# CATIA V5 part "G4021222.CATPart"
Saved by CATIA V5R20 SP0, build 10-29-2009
Part number: G4021222
Revision: 7
Definition: design
Nomenclature: G4021222
Source: made
Description: NOT SPECIFIED
Bounding box of the stored display mesh (mm): x -9 to 22, y -10.833 to 10.833, z -11 to 11
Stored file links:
  C:\Users\Raffaele\Desktop\3D X SITO CF\BOLEX\26-BUSH REF 402\G4021222.CATPart
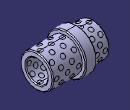
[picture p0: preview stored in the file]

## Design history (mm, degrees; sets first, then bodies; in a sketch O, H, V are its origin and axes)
Body1 "MANIFOLD_SOLID_BREP #8473" (main body)
  Solid1: solid without history
Body2 "MANIFOLD_SOLID_BREP #8616"
  Solid2: solid without history
Body3 "MANIFOLD_SOLID_BREP #8759"
  Solid3: solid without history
Body4 "MANIFOLD_SOLID_BREP #8902"
  Solid4: solid without history
Body5 "MANIFOLD_SOLID_BREP #9045"
  Solid5: solid without history
Body6 "MANIFOLD_SOLID_BREP #9190"
  Solid6: solid without history
Body7 "MANIFOLD_SOLID_BREP #9335"
  Solid7: solid without history
Body8 "MANIFOLD_SOLID_BREP #9480"
  Solid8: solid without history
Body9 "MANIFOLD_SOLID_BREP #9625"
  Solid9: solid without history
Body10 "MANIFOLD_SOLID_BREP #9768"
  Solid10: solid without history
Body11 "MANIFOLD_SOLID_BREP #9911"
  Solid11: solid without history
Body12 "MANIFOLD_SOLID_BREP #10056"
  Solid12: solid without history
Body13 "MANIFOLD_SOLID_BREP #10201"
  Solid13: solid without history
Body14 "MANIFOLD_SOLID_BREP #10346"
  Solid14: solid without history
Body15 "MANIFOLD_SOLID_BREP #10491"
  Solid15: solid without history
Body16 "MANIFOLD_SOLID_BREP #10634"
  Solid16: solid without history
Body17 "MANIFOLD_SOLID_BREP #10777"
  Solid17: solid without history
Body18 "MANIFOLD_SOLID_BREP #10922"
  Solid18: solid without history
Body19 "MANIFOLD_SOLID_BREP #11067"
  Solid19: solid without history
Body20 "MANIFOLD_SOLID_BREP #11212"
  Solid20: solid without history
Body21 "MANIFOLD_SOLID_BREP #11357"
  Solid21: solid without history
Body22 "MANIFOLD_SOLID_BREP #11502"
  Solid22: solid without history
Body23 "MANIFOLD_SOLID_BREP #11647"
  Solid23: solid without history
Body24 "MANIFOLD_SOLID_BREP #11792"
  Solid24: solid without history
Body25 "MANIFOLD_SOLID_BREP #11937"
  Solid25: solid without history
Body26 "MANIFOLD_SOLID_BREP #12082"
  Solid26: solid without history
Body27 "MANIFOLD_SOLID_BREP #12227"
  Solid27: solid without history
Body28 "MANIFOLD_SOLID_BREP #12372"
  Solid28: solid without history
Body29 "MANIFOLD_SOLID_BREP #12517"
  Solid29: solid without history
Body30 "MANIFOLD_SOLID_BREP #12660"
  Solid30: solid without history
Body31 "MANIFOLD_SOLID_BREP #12805"
  Solid31: solid without history
Body32 "MANIFOLD_SOLID_BREP #12950"
  Solid32: solid without history
Body33 "MANIFOLD_SOLID_BREP #13093"
  Solid33: solid without history
Body34 "MANIFOLD_SOLID_BREP #13236"
  Solid34: solid without history
Body35 "MANIFOLD_SOLID_BREP #13379"
  Solid35: solid without history
Body36 "MANIFOLD_SOLID_BREP #13524"
  Solid36: solid without history
Body37 "MANIFOLD_SOLID_BREP #13669"
  Solid37: solid without history
Body38 "MANIFOLD_SOLID_BREP #13814"
  Solid38: solid without history
Body39 "MANIFOLD_SOLID_BREP #13959"
  Solid39: solid without history
Body40 "MANIFOLD_SOLID_BREP #14104"
  Solid40: solid without history
Body41 "MANIFOLD_SOLID_BREP #14249"
  Solid41: solid without history
Body42 "MANIFOLD_SOLID_BREP #14394"
  Solid42: solid without history
Body43 "MANIFOLD_SOLID_BREP #14539"
  Solid43: solid without history
Body44 "MANIFOLD_SOLID_BREP #14684"
  Solid44: solid without history
Body45 "MANIFOLD_SOLID_BREP #14829"
  Solid45: solid without history
Body46 "MANIFOLD_SOLID_BREP #14974"
  Solid46: solid without history
Body47 "MANIFOLD_SOLID_BREP #15117"
  Solid47: solid without history
Body48 "MANIFOLD_SOLID_BREP #15260"
  Solid48: solid without history
Body49 "MANIFOLD_SOLID_BREP #15405"
  Solid49: solid without history
Body50 "MANIFOLD_SOLID_BREP #15550"
  Solid50: solid without history
Body51 "MANIFOLD_SOLID_BREP #15695"
  Solid51: solid without history
Body52 "MANIFOLD_SOLID_BREP #15840"
  Solid52: solid without history
Body53 "MANIFOLD_SOLID_BREP #15983"
  Solid53: solid without history
Body54 "MANIFOLD_SOLID_BREP #16126"
  Solid54: solid without history
Body55 "MANIFOLD_SOLID_BREP #16271"
  Solid55: solid without history
Body56 "MANIFOLD_SOLID_BREP #16416"
  Solid56: solid without history
Body57 "MANIFOLD_SOLID_BREP #16561"
  Solid57: solid without history
Body58 "MANIFOLD_SOLID_BREP #16706"
  Solid58: solid without history
Body59 "MANIFOLD_SOLID_BREP #16851"
  Solid59: solid without history
Body60 "MANIFOLD_SOLID_BREP #16996"
  Solid60: solid without history
Body61 "MANIFOLD_SOLID_BREP #17141"
  Solid61: solid without history
Body62 "MANIFOLD_SOLID_BREP #17284"
  Solid62: solid without history
Body63 "MANIFOLD_SOLID_BREP #17427"
  Solid63: solid without history
Body64 "MANIFOLD_SOLID_BREP #17570"
  Solid64: solid without history
Body65 "MANIFOLD_SOLID_BREP #17713"
  Solid65: solid without history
